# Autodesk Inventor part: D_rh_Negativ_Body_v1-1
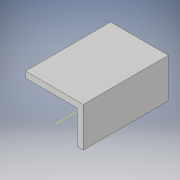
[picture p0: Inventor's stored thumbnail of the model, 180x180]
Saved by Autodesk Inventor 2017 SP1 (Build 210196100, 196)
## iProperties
Part Number: D_rh_Negativ_Body_v1-1
Material: Generisch
Document SubType Name: Modeling
Designer: haesner
Density: 1 g/cm^3
Appearance: Vorgabe
Part Number: D_rh_Negativ_Body_v1-1_3D-Druck
Author: haesner
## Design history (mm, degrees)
sketch "Skizze1"
  geometry: L1 (0, 9.5)-(-10.86, 9.5); L2 (-10.86, 9.5)-(-2, -9.5); L3 (-2, -9.5)-(0, -9.5); L4 (0, -9.5)-(0, 9.5); L5 (0, -23.059)-(0, 18.519) reference; L6 (-13.032, 0)-(2.172, 0) reference; 1 further point
  constraints: 8 end point, 1 collinear, 1 horizontal, 1 parallel, 1 perpendicular, 1 other
  dimensions: "d2" = 19 distance of L3.end L1.start; "d28" = 2 distance of L2.end L3.end; "d29" = 25 deg angle of L4 L2
extrude "Extrusion1" new body sketch "Skizze1" distance "d3" = 9; taper "d4" = 0 deg
sketch "Skizze2"
  geometry: L1 (-1, 12.579)-(-1, -17.12); L2 (0, -23.059)-(0, 18.519) reference; 1 further point
  constraints: 2 end point, 1 vertical
  dimensions: "d5" = 1 distance between parallel lines of L2 L1
workplane "Arbeitsebene1"
  workaxis "Arbeitsachse1"
feature "Trennen1"
sketch "Skizze3"
  geometry: L1 (-1, 9.5)-(-1, -9.5) reference; L2 (-1, -9.5)-(0, -9.5) reference; L3 (0, -9.5)-(0, 9.5) reference; L4 (0, 9.5)-(-1, 9.5) reference; 1 further point
extrude "Extrusion2" join sketch "Skizze3" distance "d7" = 1; taper "d8" = 0 deg
sketch "Skizze4"
  geometry: L1 (-10.86, 9.5)-(-1, 9.5) reference; L2 (0, 9.5)-(-1, 9.5) reference; L3 (0, -9.5)-(0, 9.5) reference; L4 (-1, -9.5)-(0, -9.5) reference; L5 (-1, -9.5)-(-2, -9.5) reference; L6 (-2, -9.5)-(-10.86, 9.5) reference; 1 further point
extrude "Extrusion3" join sketch "Skizze4" distance "d9" = 1; taper "d10" = 0 deg
sketch "Skizze5"
  geometry: L1 (0, 14)-(-17, 14); L2 (-17, 14)-(-17, -14); L3 (-17, -14)-(0, -14); L4 (0, -14)-(0, 14); L5 (0, -23.744)-(0, 22.624) reference; L6 (-20.4, 0)-(3.4, 0) reference; 1 further point
  constraints: 8 end point, 2 parallel, 1 collinear, 1 horizontal, 1 perpendicular, 1 other
  dimensions: "d11" = 28 distance of L3.end L1.start; "d12" = 17 distance of L1.start L1.end
extrude "Extrusion4" join sketch "Skizze5" distance "d13" = 2; taper "d14" = 0 deg
sketch "Skizze6"
  geometry: L1 (-11, 23.5)-(-13, 23.5) reference; L2 (-11, -4.5)-(-13, -4.5) reference; L3 (-11, 23.5)-(-11, 23.5); L4 (-11, 23.5)-(0, 23.5); L5 (0, 23.5)-(0, -4.5); L6 (0, -4.5)-(-11, -4.5); L7 (-11, -4.5)-(-11, -4.5); L8 (-13, -4.5)-(-13, 23.5) reference; L9 (2.6, 9.5)-(-15.6, 9.5) reference; L10 (0, -14.244)-(0, 32.124) reference; L11 (-11, 19)-(-11, 23.5) reference; L12 (-11, -4.5)-(-11, 0) reference; 1 further point
  constraints: 10 end point, 2 collinear, 2 perpendicular, 1 parallel, 1 other
  dimensions: "d15" = 28 distance of L4.end L5.end
extrude "Extrusion5" join sketch "Skizze6" distance "d16" = 2; taper "d17" = 0 deg
node "Volumenkörper1"
node "Projizierte Kontur1"
other parameters: "d6" = 40 deg
